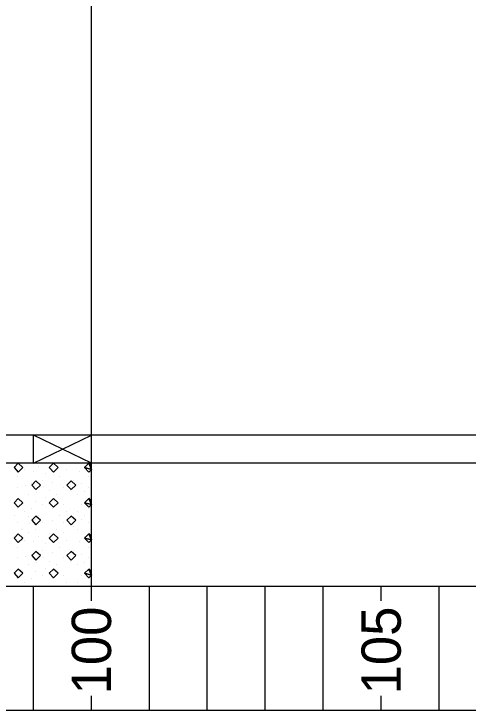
# Model space of a CAD drawing. Extents: x 1313964 to 1316843, y 2087046 to 2096619.
# Drawn here: x 1313998.03 to 1314005.87, y 2089928.16 to 2089940.17 of the extents above; entities that cross this region are included whole.
import ezdxf

# ---------------------------------------------------------------- set-up
doc = ezdxf.new("R2010")
doc.units = 0
doc.layers.add('B-Sub-Contour', color=7, linetype='Continuous')
doc.layers.add('Default', color=7, linetype='Continuous')

# ---------------------------------------------------------------- blocks, each defined once
blk = doc.blocks.new('POINT_DISPLAY')
at = {"layer": 'Default'}
blk.add_line((0, 0), (0, 0), dxfattribs=at)

msp = doc.modelspace()

# ---------------------------------------------------------------- linework, layer by layer
at = {"layer": 'B-Sub-Contour'}
for points in [[(1314036.804, 2089928.164), (1314036.804, 2089971.035), (1313975.385, 2089971.035), (1313975.385, 2089928.164), (1314036.804, 2089928.164)], [(1313999.372, 2089932.907), (1313999.372, 2089948.779)], [(1314034.372, 2089932.907), (1313989.372, 2089932.907)], [(1313998.372, 2089932.421), (1313999.372, 2089932.907)], [(1313999.372, 2089932.421), (1313998.372, 2089932.907)], [(1313998.372, 2089932.421), (1313998.372, 2089932.907)], [(1313999.372, 2089932.421), (1313999.372, 2089932.907)], [(1313999.372, 2089932.421), (1313999.372, 2089932.907)], [(1314034.372, 2089932.421), (1313982.683, 2089932.421)], [(1313999.372, 2089930.292), (1313999.372, 2089932.421)], [(1314034.372, 2089930.292), (1313982.683, 2089930.292)], [(1313998.372, 2089928.164), (1313998.372, 2089930.292)], [(1313999.372, 2089930.049), (1313999.372, 2089930.292)], [(1313999.372, 2089930.049), (1313999.372, 2089930.292)], [(1314000.372, 2089928.164), (1314000.372, 2089930.292)], [(1314001.372, 2089928.164), (1314001.372, 2089930.292)], [(1314001.372, 2089928.164), (1314001.372, 2089930.292)], [(1314002.372, 2089928.164), (1314002.372, 2089930.292)], [(1314003.372, 2089928.164), (1314003.372, 2089930.292)], [(1314003.372, 2089928.164), (1314003.372, 2089930.292)], [(1314004.372, 2089930.049), (1314004.372, 2089930.292)], [(1314005.372, 2089928.164), (1314005.372, 2089930.292)], [(1314005.372, 2089928.164), (1314005.372, 2089930.292)], [(1313999.372, 2089928.164), (1313999.372, 2089928.407)], [(1313999.372, 2089928.164), (1313999.372, 2089928.407)], [(1314004.372, 2089928.164), (1314004.372, 2089928.407)]]:
    msp.add_lwpolyline(points, dxfattribs=at)
for points in [[(1313998.11, 2089932.421), (1313998.037, 2089932.348), (1313998.11, 2089932.269), (1313998.189, 2089932.348)], [(1313998.718, 2089932.421), (1313998.645, 2089932.348), (1313998.718, 2089932.269), (1313998.797, 2089932.348)], [(1313999.372, 2089932.314), (1313999.326, 2089932.421), (1313999.253, 2089932.348), (1313999.372, 2089932.314)], [(1313999.372, 2089932.379), (1313999.327, 2089932.421), (1313999.326, 2089932.421), (1313999.372, 2089932.379)], [(1313999.372, 2089932.314), (1313999.372, 2089932.379), (1313999.326, 2089932.421), (1313999.372, 2089932.314)], [(1313999.326, 2089932.269), (1313999.372, 2089932.314), (1313999.253, 2089932.348), (1313999.326, 2089932.269)], [(1313998.414, 2089932.117), (1313998.341, 2089932.044), (1313998.414, 2089931.965), (1313998.493, 2089932.044)], [(1313999.022, 2089932.117), (1313998.949, 2089932.044), (1313999.022, 2089931.965), (1313999.101, 2089932.044)], [(1313998.11, 2089931.813), (1313998.037, 2089931.74), (1313998.11, 2089931.661), (1313998.189, 2089931.74)], [(1313998.718, 2089931.813), (1313998.645, 2089931.74), (1313998.718, 2089931.661), (1313998.797, 2089931.74)], [(1313999.372, 2089931.706), (1313999.326, 2089931.813), (1313999.253, 2089931.74), (1313999.372, 2089931.706)], [(1313999.372, 2089931.706), (1313999.372, 2089931.771), (1313999.326, 2089931.813), (1313999.372, 2089931.706)], [(1313999.326, 2089931.661), (1313999.372, 2089931.706), (1313999.253, 2089931.74), (1313999.326, 2089931.661)], [(1313998.414, 2089931.508), (1313998.341, 2089931.436), (1313998.414, 2089931.356), (1313998.493, 2089931.436)], [(1313999.022, 2089931.508), (1313998.949, 2089931.436), (1313999.022, 2089931.356), (1313999.101, 2089931.436)], [(1313998.11, 2089931.204), (1313998.037, 2089931.131), (1313998.11, 2089931.052), (1313998.189, 2089931.131)], [(1313998.718, 2089931.204), (1313998.645, 2089931.131), (1313998.718, 2089931.052), (1313998.797, 2089931.131)], [(1313999.372, 2089931.098), (1313999.326, 2089931.204), (1313999.253, 2089931.131), (1313999.372, 2089931.098)], [(1313999.372, 2089931.098), (1313999.372, 2089931.163), (1313999.326, 2089931.204), (1313999.372, 2089931.098)], [(1313999.326, 2089931.052), (1313999.372, 2089931.098), (1313999.253, 2089931.131), (1313999.326, 2089931.052)], [(1313998.414, 2089930.9), (1313998.341, 2089930.827), (1313998.414, 2089930.748), (1313998.493, 2089930.827)], [(1313999.022, 2089930.9), (1313998.949, 2089930.827), (1313999.022, 2089930.748), (1313999.101, 2089930.827)], [(1313998.11, 2089930.596), (1313998.037, 2089930.523), (1313998.11, 2089930.444), (1313998.189, 2089930.523)], [(1313998.718, 2089930.596), (1313998.645, 2089930.523), (1313998.718, 2089930.444), (1313998.797, 2089930.523)], [(1313999.372, 2089930.49), (1313999.326, 2089930.596), (1313999.253, 2089930.523), (1313999.372, 2089930.49)], [(1313999.372, 2089930.49), (1313999.372, 2089930.555), (1313999.326, 2089930.596), (1313999.372, 2089930.49)], [(1313999.326, 2089930.444), (1313999.372, 2089930.49), (1313999.253, 2089930.523), (1313999.326, 2089930.444)]]:
    msp.add_lwpolyline(points, close=True, dxfattribs=at)

# ---------------------------------------------------------------- block references
at = {"layer": 'B-Sub-Contour', "xscale": 0.019951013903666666, "yscale": 0.019951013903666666, "rotation": 90}
for p in [(1313998.037, 2089932.37), (1313998.463, 2089932.37), (1313999.253, 2089932.37), (1313998.22, 2089932.31), (1313998.374, 2089932.282), (1313998.585, 2089932.249), (1313998.706, 2089932.31), (1313998.949, 2089932.31), (1313999.162, 2089932.285), (1313998.098, 2089932.188), (1313998.524, 2089932.127), (1313998.828, 2089932.188), (1313999.071, 2089932.127), (1313999.314, 2089932.188), (1313998.098, 2089932.006), (1313998.236, 2089932.036), (1313998.341, 2089932.066), (1313998.549, 2089932.011), (1313998.706, 2089932.089), (1313998.889, 2089932.006), (1313999.193, 2089932.066), (1313999.314, 2089932.006), (1313998.28, 2089931.884), (1313998.421, 2089931.918), (1313998.645, 2089931.945), (1313998.767, 2089931.884), (1313999.01, 2089931.945), (1313999.132, 2089931.884), (1313999.248, 2089931.926), (1313998.585, 2089931.823), (1313998.159, 2089931.762), (1313998.402, 2089931.762), (1313998.524, 2089931.702), (1313998.889, 2089931.702), (1313999.193, 2089931.702), (1313998.098, 2089931.641), (1313998.22, 2089931.58), (1313998.341, 2089931.641), (1313998.706, 2089931.641), (1313998.949, 2089931.58), (1313999.132, 2089931.58), (1313999.314, 2089931.641), (1313998.037, 2089931.519), (1313998.28, 2089931.498), (1313998.402, 2089931.458), (1313998.463, 2089931.519), (1313998.692, 2089931.441), (1313998.828, 2089931.519), (1313999.01, 2089931.505), (1313999.193, 2089931.458), (1313999.253, 2089931.519), (1313998.098, 2089931.398), (1313998.297, 2089931.378), (1313998.524, 2089931.398), (1313998.889, 2089931.398), (1313999.071, 2089931.337), (1313999.314, 2089931.398), (1313998.159, 2089931.276), (1313998.289, 2089931.231), (1313998.402, 2089931.276), (1313998.645, 2089931.215), (1313998.767, 2089931.276), (1313998.889, 2089931.218), (1313999.132, 2089931.276), (1313998.037, 2089931.154), (1313998.22, 2089931.093), (1313998.374, 2089931.066), (1313998.463, 2089931.154), (1313998.706, 2089931.093), (1313998.949, 2089931.093), (1313999.162, 2089931.069), (1313999.253, 2089931.154), (1313998.098, 2089930.972), (1313998.585, 2089931.033), (1313998.828, 2089930.972), (1313999.314, 2089930.972), (1313998.236, 2089930.82), (1313998.341, 2089930.85), (1313998.524, 2089930.911), (1313998.706, 2089930.873), (1313999.071, 2089930.911), (1313999.193, 2089930.85), (1313998.098, 2089930.789), (1313998.421, 2089930.701), (1313998.549, 2089930.795), (1313998.645, 2089930.729), (1313998.889, 2089930.789), (1313999.01, 2089930.729), (1313999.248, 2089930.71), (1313999.314, 2089930.789), (1313998.28, 2089930.668), (1313998.585, 2089930.607), (1313998.767, 2089930.668), (1313999.132, 2089930.668), (1313998.159, 2089930.546), (1313998.402, 2089930.546), (1313998.524, 2089930.485), (1313998.889, 2089930.485), (1313999.193, 2089930.485), (1313998.098, 2089930.425), (1313998.22, 2089930.364), (1313998.341, 2089930.425), (1313998.706, 2089930.425), (1313998.949, 2089930.364), (1313999.132, 2089930.364), (1313999.314, 2089930.425), (1313998.037, 2089930.303), (1313998.463, 2089930.303), (1313998.828, 2089930.303), (1313999.253, 2089930.303)]:
    msp.add_blockref('POINT_DISPLAY', p, dxfattribs=at)

# ---------------------------------------------------------------- texts
at = {"layer": 'B-Sub-Contour'}
for s, p in [('100', (1313999.711, 2089928.434)), ('100', (1313999.711, 2089928.434)), ('105', (1314004.711, 2089928.434))]:
    msp.add_text(s, height=0.6786, rotation=90, dxfattribs=at).set_placement(p)

doc.saveas('drawing.dxf')
